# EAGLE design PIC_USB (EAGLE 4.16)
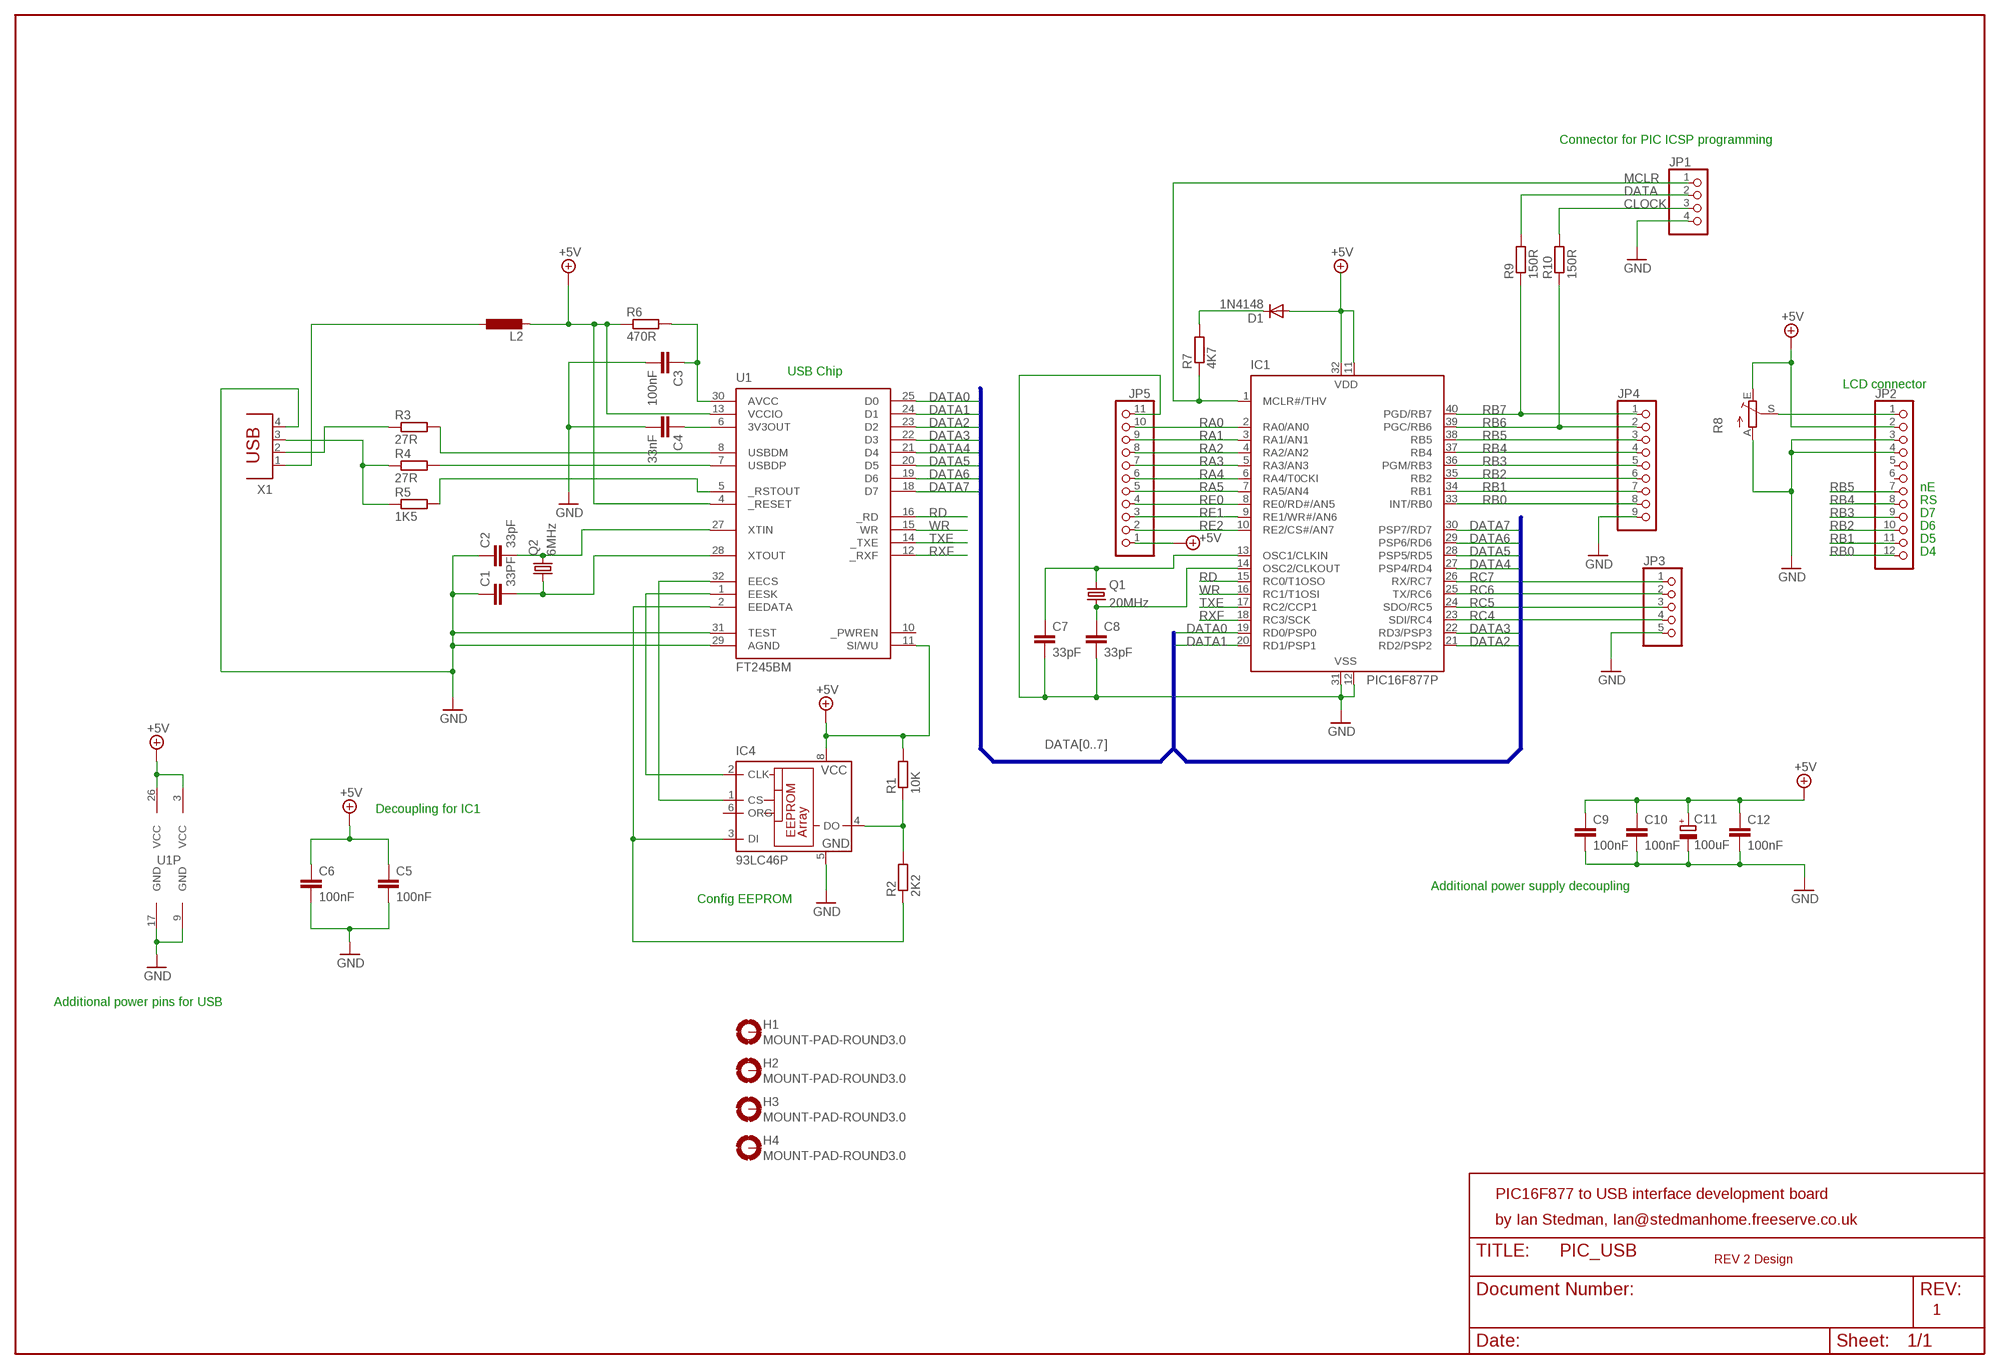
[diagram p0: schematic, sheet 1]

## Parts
C1  33PF  C-EU025-025X050  [C025-025X050]
C2  33pF  C-EU025-025X050  [C025-025X050]
C3  100nF  C-EU050-025X075  [C050-025X075]
C4  33nF  C-EU050-025X075  [C050-025X075]
C5  100nF  C-EU050-025X075  [C050-025X075]
C6  100nF  C-EU050-025X075  [C050-025X075]
C7  33pF  C-EU025-025X050  [C025-025X050]
C8  33pF  C-EU025-025X050  [C025-025X050]
C9  100nF  C-EU050-025X075  [C050-025X075]
C10  100nF  C-EU050-025X075  [C050-025X075]
C11  100uF  CPOL-EUE5-10.5  [E5-10,5]
C12  100nF  C-EU050-025X075  [C050-025X075]
D1  1N4148  [DO35-10]
H1  MOUNT-PAD-ROUND3.0  [3,0-PAD]
H2  MOUNT-PAD-ROUND3.0  [3,0-PAD]
H3  MOUNT-PAD-ROUND3.0  [3,0-PAD]
H4  MOUNT-PAD-ROUND3.0  [3,0-PAD]
IC1  PIC16F877P  [DIL40]
IC4  93LC46P  [DIL8]
JP1  PINHD-1X4  [1X04]
JP2  PINHD-1X12  [1X12]
JP3  PINHD-1X5  [1X05]
JP4  PINHD-1X9  [1X09]
JP5  PINHD-1X11  [1X11]
L2  L-EU0207/10  [0207/10]
Q1  20MHz  CRYTALHC49U-V  [HC49U-V]
Q2  6MHz  CRYTALHC49U-V  [HC49U-V]
R1  10K  R-EU_0207/7  [0207/7]
R2  2K2  R-EU_0207/7  [0207/7]
R3  27R  R-EU_0207/7  [0207/7]
R4  27R  R-EU_0207/7  [0207/7]
R5  1K5  R-EU_0207/7  [0207/7]
R6  470R  R-EU_0207/7  [0207/7]
R7  4K7  R-EU_0207/7  [0207/7]
R8  TRIM_EU-CA6V  [CA6V]
R9  150R  R-EU_0207/2V  [0207/2V]
R10  150R  R-EU_0207/5V  [0207/5V]
U1  FT245BM  [LQFP32]
X1  PN61729  [PN61729]

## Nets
3V3OUT: C4.1 U1.6(3V3OUT)
+5V: C5.1 C6.1 C9.1 C10.1 C11.+ C12.1 D1.A IC1.11(VDD) IC1.32(VDD) IC4.8(VCC) JP2.2 JP5.1 L2.2 R1.2 R6.1 R8.E U1.3(VCC) U1.4(_RESET) U1.11(SI/WU) U1.13(VCCIO) U1.26(VCC)
AVCC: C3.1 R6.2 U1.30(AVCC)
CLOCK: JP1.3 R10.2
DATA: JP1.2 R9.2
DATA0: IC1.19(RD0/PSP0) U1.25(D0)
DATA1: IC1.20(RD1/PSP1) U1.24(D1)
DATA2: IC1.21(RD2/PSP2) U1.23(D2)
DATA3: IC1.22(RD3/PSP3) U1.22(D3)
DATA4: IC1.27(PSP4/RD4) U1.21(D4)
DATA5: IC1.28(PSP5/RD5) U1.20(D5)
DATA6: IC1.29(PSP6/RD6) U1.19(D6)
DATA7: IC1.30(PSP7/RD7) U1.18(D7)
GND: C1.1 C2.1 C3.2 C4.2 C5.2 C6.2 C7.2 C8.2 C9.2 C10.2 C11.- C12.2 IC1.12(VSS) IC1.31(VSS) IC4.5(GND) JP1.4 JP2.3 JP2.4 JP3.5 JP4.9 JP5.11 R8.A U1.9(GND) U1.17(GND) U1.29(AGND) U1.31(TEST) X1.4
MCLR: IC1.1(MCLR#/THV) JP1.1 R7.1
N$1: D1.C R7.2
N$2: C1.2 Q2.1 U1.28(XTOUT)
N$3: C7.1 IC1.13(OSC1/CLKIN) Q1.2
N$5: JP2.1 R8.S
N$8: C2.2 Q2.2 U1.27(XTIN)
N$9: C8.1 IC1.14(OSC2/CLKOUT) Q1.1
N$10: IC4.1(CS) U1.32(EECS)
N$11: IC4.2(CLK) U1.1(EESK)
N$12: IC4.3(DI) R2.1 U1.2(EEDATA)
N$15: IC4.4(DO) R1.1 R2.2
N$19: R3.2 U1.8(USBDM)
N$20: R4.2 U1.7(USBDP)
N$22: R5.2 U1.5(_RSTOUT)
PWRIN: L2.1 X1.1
RA0: IC1.2(RA0/AN0) JP5.10
RA1: IC1.3(RA1/AN1) JP5.9
RA2: IC1.4(RA2/AN2) JP5.8
RA3: IC1.5(RA3/AN3) JP5.7
RA4: IC1.6(RA4/T0CKI) JP5.6
RA5: IC1.7(RA5/AN4) JP5.5
RB0: IC1.33(INT/RB0) JP2.12 JP4.8
RB1: IC1.34(RB1) JP2.11 JP4.7
RB2: IC1.35(RB2) JP2.10 JP4.6
RB3: IC1.36(PGM/RB3) JP2.9 JP4.5
RB4: IC1.37(RB4) JP2.8 JP4.4
RB5: IC1.38(RB5) JP2.7 JP4.3
RB6: IC1.39(PGC/RB6) JP4.2 R10.1
RB7: IC1.40(PGD/RB7) JP4.1 R9.1
RC4: IC1.23(SDI/RC4) JP3.4
RC5: IC1.24(SDO/RC5) JP3.3
RC6: IC1.25(TX/RC6) JP3.2
RC7: IC1.26(RX/RC7) JP3.1
RD: IC1.15(RC0/T1OSO) U1.16(_RD)
RE0: IC1.8(RE0/RD#/AN5) JP5.4
RE1: IC1.9(RE1/WR#/AN6) JP5.3
RE2: IC1.10(RE2/CS#/AN7) JP5.2
RXF: IC1.18(RC3/SCK) U1.12(_RXF)
TXE: IC1.17(RC2/CCP1) U1.14(_TXE)
USBM: R3.1 X1.2
USBP: R4.1 R5.1 X1.3
WR: IC1.16(RC1/T1OSI) U1.15(WR)
Unconnected: H1.B3,0(MOUNT) H2.B3,0(MOUNT) H3.B3,0(MOUNT) H4.B3,0(MOUNT) IC4.6(ORG) IC4.7(NU) JP2.5 JP2.6 U1.10(_PWREN)

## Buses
DATA[0..7]

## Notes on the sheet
- Connector for PIC ICSP programming
- USB Chip
- LCD connector
- nE
- RS
- D7
- D6
- D5
- D4
- Decoupling for IC1
- Additional power supply decoupling
- Config EEPROM
- Additional power pins for USB
- PIC16F877 to USB interface development board
- by Ian Stedman, Ian@stedmanhome.freeserve.co.uk
- REV 2 Design
- 1

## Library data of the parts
C1-C10 C12 = rcl:C-EU: CAPACITOR, European symbol
C11 = rcl:CPOL-EU: POLARIZED CAPACITOR, European symbol
D1 = diode:1N4148: DIODE
H1-H4 = holes:MOUNT-PAD-ROUND: MOUNTING PAD, round
IC1 = microchip:PIC16F87*: MICROCONTROLLER
IC4 = microchip:93*: Serial EPROM 1 K/2 K/4 K, low voltage, Microwire
JP1 = pinhead:PINHD-1X4: PIN HEADER
JP2 = pinhead:PINHD-1X12: PIN HEADER
JP3 = pinhead:PINHD-1X5: PIN HEADER
JP4 = pinhead:PINHD-1X9: PIN HEADER
JP5 = pinhead:PINHD-1X11: PIN HEADER
L2 = rcl:L-EU: INDUCTOR, European symbol
Q1 Q2 = crystal:CRYTAL: CRYSTAL
R1-R7 R9 R10 = rcl:R-EU_: RESISTOR, European symbol
R8 = pot:TRIM_EU-: POTENTIOMETER
U1 = ftdi3:FT245BM: USB FIFO 2nd Generation USB FIFO (USB <-> Parallel)
X1 = con-berg:PN61729: BERG

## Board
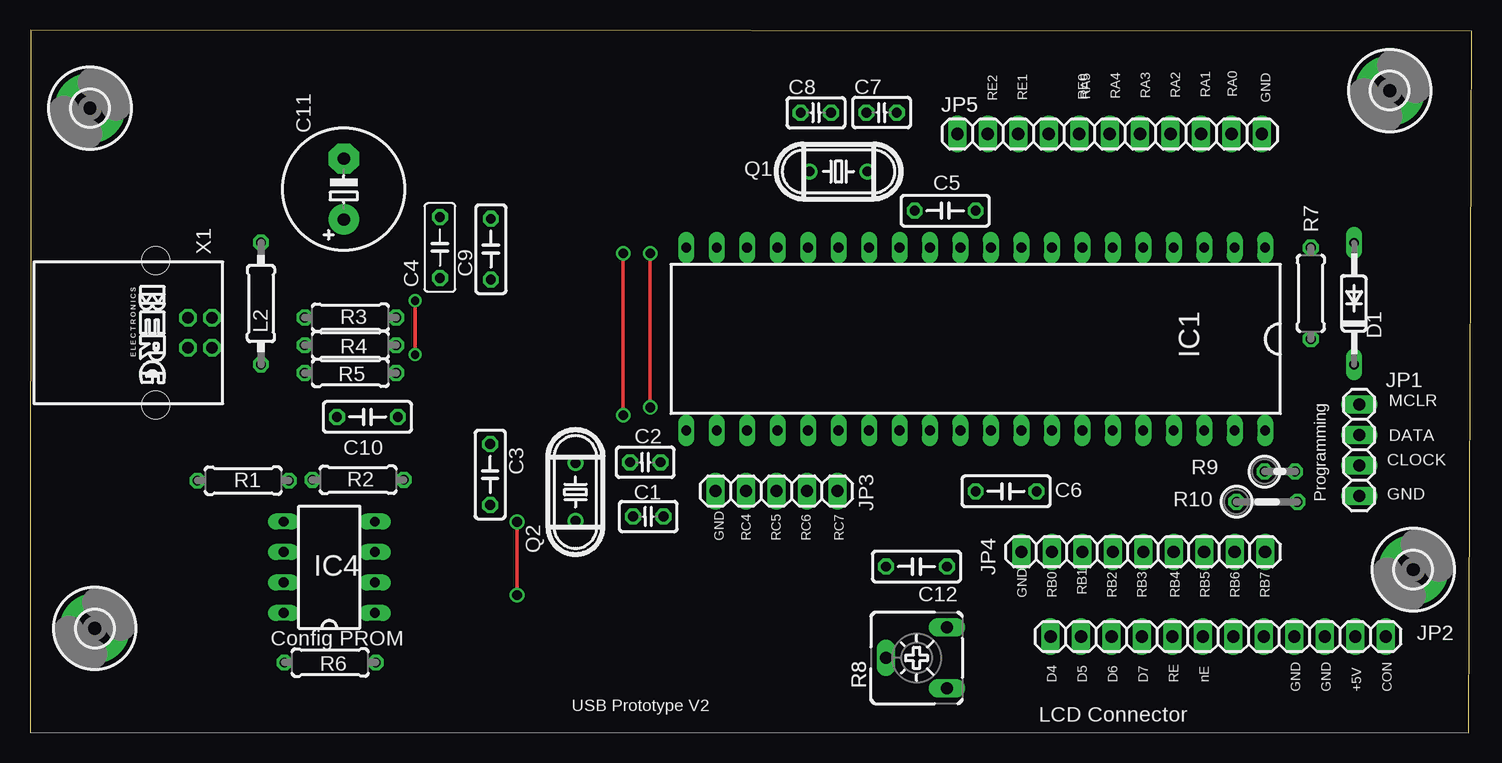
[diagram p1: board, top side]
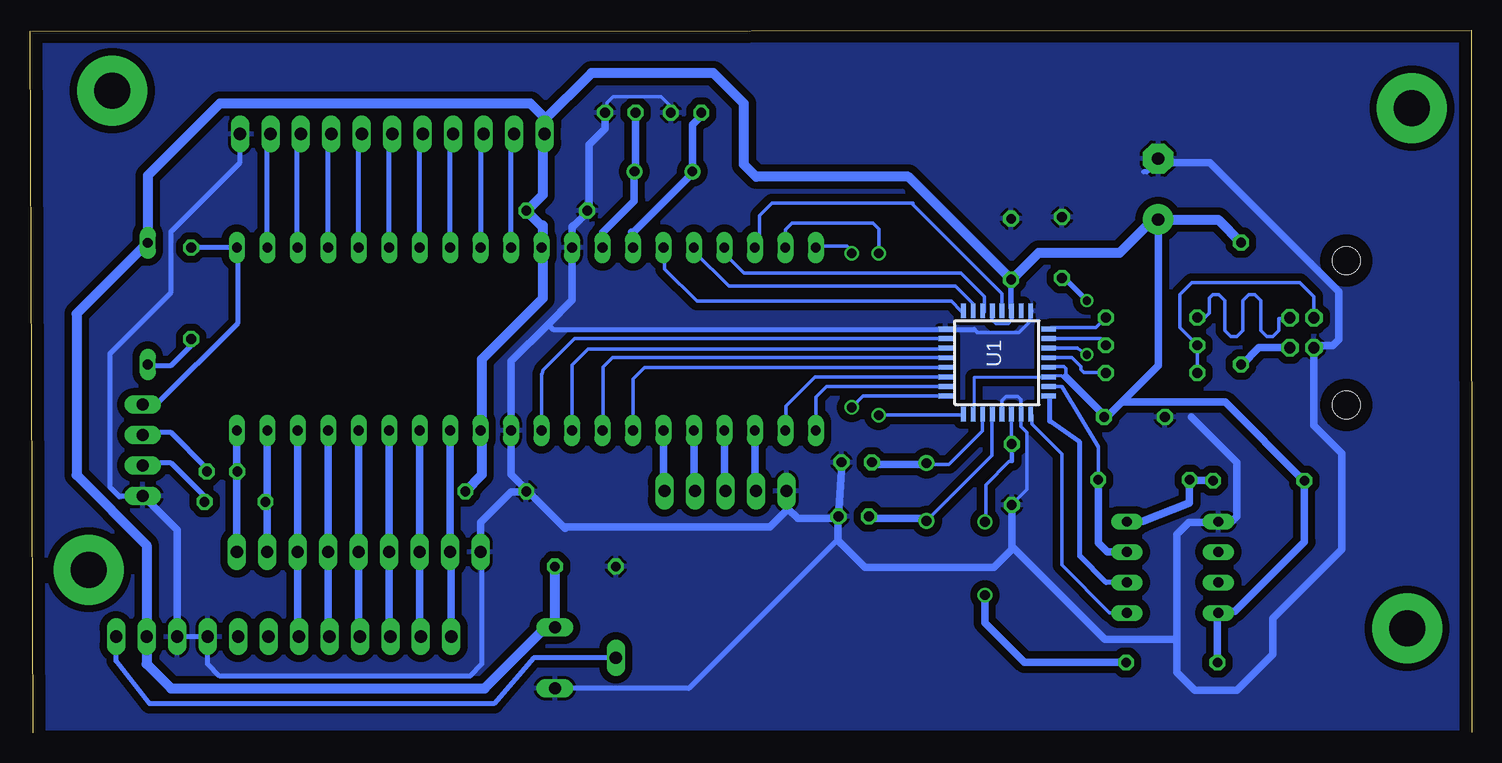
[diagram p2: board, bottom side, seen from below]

Size 120.2 x 58.59 mm. Coordinates in mm from the lower left corner, seen from the top.
Outline: 119.94,0 120.2,58.5 0.05,58.59 0,0.04
Copper layers (1*16): Top 0.035mm / dielectric 1.5mm / Bottom 0.035mm
Design rules "10mils": minimum track width 10mil, minimum drill 24mil, track to track 10mil, track to pad 10mil, pad to pad 10mil, via to via 10mil, smd to smd 10mil, copper to edge 40mil, drill to drill 10mil, minimum pad ring 10mil, minimum via ring 8mil, stop-mask expansion 0mil, vias tented up to drill 0mil, thermal gap 10mil

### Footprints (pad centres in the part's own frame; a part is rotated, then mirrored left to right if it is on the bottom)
C025-025X050 = drill 0.813 octagon: 1 -1.27,0; 2 1.27,0
C050-025X075 = drill 0.813 octagon: 1 -2.54,0; 2 2.54,0
E5-10,5 = drill 1.016 pad 2.54 round: + -2.54,0 | drill 1.016 pad 2.54 octagon: - 2.54,0
DO35-10 = drill 0.813 long: A 5.08,0; C -5.08,0
3,0-PAD = drill 3 pad 5.842 round: B3,0 0,0
DIL40 = drill 0.813 long: 1 -24.13,-7.62; 2 -21.59,-7.62; 3 -19.05,-7.62; 4 -16.51,-7.62; 5 -13.97,-7.62; 6 -11.43,-7.62; 7 -8.89,-7.62; 8 -6.35,-7.62; 9 -3.81,-7.62; 10 -1.27,-7.62; 11 1.27,-7.62; 12 3.81,-7.62; 13 6.35,-7.62; 14 8.89,-7.62; 15 11.43,-7.62; 16 13.97,-7.62; 17 16.51,-7.62; 18 19.05,-7.62; 19 21.59,-7.62; 20 24.13,-7.62; 21 24.13,7.62; 22 21.59,7.62; 23 19.05,7.62; 24 16.51,7.62; 25 13.97,7.62; 26 11.43,7.62; 27 8.89,7.62; 28 6.35,7.62; 29 3.81,7.62; 30 1.27,7.62; 31 -1.27,7.62; 32 -3.81,7.62; 33 -6.35,7.62; 34 -8.89,7.62; 35 -11.43,7.62; 36 -13.97,7.62; 37 -16.51,7.62; 38 -19.05,7.62; 39 -21.59,7.62; 40 -24.13,7.62
DIL8 = drill 0.813 long: 1 -3.81,-3.81; 2 -1.27,-3.81; 3 1.27,-3.81; 4 3.81,-3.81; 5 3.81,3.81; 6 1.27,3.81; 7 -1.27,3.81; 8 -3.81,3.81
1X04 = drill 1.016 long: 1 -3.81,0; 2 -1.27,0; 3 1.27,0; 4 3.81,0
1X12 = drill 1.016 long: 1 -13.97,0; 2 -11.43,0; 3 -8.89,0; 4 -6.35,0; 5 -3.81,0; 6 -1.27,0; 7 1.27,0; 8 3.81,0; 9 6.35,0; 10 8.89,0; 11 11.43,0; 12 13.97,0
1X05 = drill 1.016 long: 1 -5.08,0; 2 -2.54,0; 3 0,0; 4 2.54,0; 5 5.08,0
1X09 = drill 1.016 long: 1 -10.16,0; 2 -7.62,0; 3 -5.08,0; 4 -2.54,0; 5 0,0; 6 2.54,0; 7 5.08,0; 8 7.62,0; 9 10.16,0
1X11 = drill 1.016 long: 1 -12.7,0; 2 -10.16,0; 3 -7.62,0; 4 -5.08,0; 5 -2.54,0; 6 0,0; 7 2.54,0; 8 5.08,0; 9 7.62,0; 10 10.16,0; 11 12.7,0
0207/10 = drill 0.813 octagon: 1 -5.08,0; 2 5.08,0
HC49U-V = drill 0.813 round: 1 -2.413,0; 2 2.413,0
0207/7 = drill 0.813 octagon: 1 -3.81,0; 2 3.81,0
CA6V = drill 1.016 long: A -2.54,-2.54; E 2.54,-2.54; S 0,2.54
0207/2V = drill 0.813 octagon: 1 -1.27,0; 2 1.27,0
0207/5V = drill 0.813 octagon: 1 -2.54,0; 2 2.54,0
LQFP32 = smd 0.4 x 1.2: 1 -2.8,-4.3; 2 -2,-4.3; 3 -1.2,-4.3; 4 -0.4,-4.3; 5 0.4,-4.3; 6 1.2,-4.3; 7 2,-4.3; 8 2.8,-4.3; 17 2.8,4.3; 18 2,4.3; 19 1.2,4.3; 20 0.4,4.3; 21 -0.4,4.3; 22 -1.2,4.3; 23 -2,4.3; 24 -2.8,4.3 | smd 1.2 x 0.4: 9 4.3,-2.8; 10 4.3,-2; 11 4.3,-1.2; 12 4.3,-0.4; 13 4.3,0.4; 14 4.3,1.2; 15 4.3,2; 16 4.3,2.8; 25 -4.3,2.8; 26 -4.3,2; 27 -4.3,1.2; 28 -4.3,0.4; 29 -4.3,-0.4; 30 -4.3,-1.2; 31 -4.3,-2; 32 -4.3,-2.8
PN61729 = drill 0.95 octagon: 1 1.25,4.71; 2 -1.25,4.71; 3 -1.25,2.71; 4 1.25,2.71 | hole 2.3: -6.02,0; 6.02,0

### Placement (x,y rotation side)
C1  51.54,18.02 180 top
C2  51.29,22.54 180 top
C3  38.36,21.52 270 top
C4  34.17,40.45 90 top
C5  76.29,43.52 180 top
C6  81.37,20.12 180 top
C7  70.99,51.7 0 top
C8  65.51,51.69 0 top
C9  38.42,40.31 90 top
C10  28.13,26.32 180 top
C11  26.16,45.32 90 top
C12  73.9,13.85 180 top
D1  110.38,35.77 90 top
H1  5,52.07 0 top
H2  5.4,8.69 0 top
H3  115.31,13.58 0 top
H4  113.35,53.53 0 top
IC1  78.83,32.82 180 top
IC4  24.95,13.79 90 top
JP1  110.81,23.55 270 top
JP2  99.05,8.01 180 top
JP3  62.23,20.14 180 top
JP4  92.8,15.07 180 top
JP5  90,49.92 0 top
L2  19.25,35.78 90 top
Q1  67.4,46.79 0 top
Q2  45.47,20.06 90 top
R1  17.77,21.01 180 top
R2  27.35,21.08 180 top
R3  26.71,34.61 0 top
R4  26.71,32.3 0 top
R5  26.71,29.99 0 top
R6  25.02,5.84 0 top
R7  106.77,36.63 270 top
R8  73.9,6.23 90 top
R9  104.19,21.77 0 top
R10  103.11,19.24 0 top
U1  39.58,30.86 90 bottom
X1  10.47,33.34 270 top

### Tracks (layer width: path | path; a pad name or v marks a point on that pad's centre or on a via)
3V3OUT  (via drill 0.7)
  Top 0.305: v32.1,31.52 v32.1,36.02
  Bottom 0.305: U1.6 32.89,32.06 32.85,32.02 v32.1,31.52
  Bottom 0.406: 34.28,37.98 34.24,37.98 | 34.24,37.98 C4.1 | v32.1,36.02 34.06,37.98 34.24,37.98
+5V
  Bottom 0.254: 39.7,34.12 38.9,34.12 38.85,34.17 38.6,34.17 38.34,34.42 38.34,37.22 38.6,37.47 36.06,40.01 29.45,40.01 26.91,42.55 26.41,42.55 26.15,42.8 | U1.26 41.5,27.12 41.5,29.62 35.8,29.62 U1.3 34.7,29.72 34.2,29.72 34.11,29.66
  Bottom 0.305: 38.42,35.09 38.4,35.07 38.38,35.09 U1.11 38.38,34.39 38.65,34.12 39.7,34.12 40,34.42 40,35.02 39.98,35.04 U1.13 | U1.4 35.26,30.46 35.2,30.52 34,30.52 33.85,30.37 33.85,29.92 34.11,29.66 33.84,29.66 | 13.9,21.02 13.91,21.01 R1.2 | 30.67,26.49 C10.1 30.44,26.32 30.22,26.55 29.2,27.56 | 77.46,42.3 77.97,42.3 78.98,43.31
  Bottom 0.406: U1.11 38.38,35.24 38.35,35.27 38.42,35.34 C9.1 | D1.A 110.4,40.85 | JP2.2 110.73,8.26
  Bottom 0.61: 21.01,9.98 21,9.97 21.21,9.76 R6.1 | 21.01,9.98 IC4.8 | 13.61,21.01 R1.2 13.96,20.96 | 13.96,20.96 13.96,15.91 19.75,10.12 21.25,10.12 21.11,9.98 21.01,9.98 | 38.6,38.02 38.42,37.84 C9.1 38.39,37.77 38.34,37.72 | 26.35,42.77 C11.+ | 77.46,49.92 77.46,51.44 | 78.83,43.47 78.98,43.31 | 78.83,43.47 C5.1 | 77.46,44.84 78.83,43.47 | 77.46,42.15 77.46,40.34 | 82.54,25.1 IC1.32 82.54,25.3 | 77.46,40.34 IC1.11 | 77.46,36.2 77.46,40.34 | 30.67,26.49 33.84,29.66 | 29.2,27.56 20.56,27.56 13.96,20.96 | 26.15,42.8 26.15,30.61 30.22,26.55
  Bottom 0.813: L2.2 21.16,42.77 C11.+ | 26.35,42.77 26.6,42.77 29.35,40.02 36.1,40.02 38.35,37.77 C9.1 | D1.A 110.38,46.46 104.38,52.46 78.48,52.46 77.46,51.44 | 77.46,49.92 JP5.1 | 77.46,49.92 77.46,44.84 78.98,43.31 | C5.1 77.46,42.15 | C6.1 82.54,21.49 82.54,25.1 | 82.54,25.3 82.54,31.12 77.46,36.2 77.46,42.3 | 77.46,49.92 77.46,50.93 73.4,55 63.24,55 60.7,52.46 60.7,47.38 59.68,46.36 46.98,46.36 38.39,37.77 | 110.4,40.85 116.32,34.93 116.32,21.47 110.48,15.63 JP2.2 110.48,5.72 108.45,3.69 82.29,3.69 77.21,8.77 R8.E C12.1
AVCC  (via drill 0.81)
  Top 0.305: v40.6,11.47 v40.6,17.57
  Bottom 0.305: 38.32,22.59 C3.1 | U1.30 38.38,22.65 38.32,22.59 | 38.32,22.59 38.58,22.59 40.5,20.67 40.5,17.67 v40.6,17.57
  Bottom 0.61: v40.6,11.47 40.6,9.17 37.3,5.87 29,5.87 28.9,5.77 R6.2
CLOCK
  Bottom 0.406: R10.2 105.65,19.69 108.45,22.48 110.99,22.48 110.81,22.31 JP1.3
DATA
  Bottom 0.406: R9.2 105.46,22.04 108.45,25.02 110.99,25.02 110.81,24.85 JP1.2
DATA0  (via drill 0.81)
  Top 0.305: v49.45,26.47 v49.45,39.97
  Bottom 0.305: IC1.19 57.24,41.93 56.7,42.47 49.95,42.47 49.45,41.97 v49.45,39.97 | U1.25 42.38,26.54 42.45,26.47 v49.45,26.47
DATA1  (via drill 0.81, 0.81 pad 0.61)
  Top 0.305: v51.7,27.12 v51.7,39.97
  Bottom 0.305: IC1.20 54.57,40.57 52.1,40.57 51.7,40.17 v51.7,39.97 | U1.24 50.75,28.07 v51.7,27.12
DATA2
  Bottom 0.305: U1.23 53.81,28.86 54.7,27.97 IC1.21 54.7,24.97
DATA3
  Bottom 0.305: U1.22 54.76,29.66 57.2,27.22 57.2,24.97 57.24,25.01 IC1.22
DATA4
  Bottom 0.305: U1.21 68.96,30.46 69.95,29.47 69.95,25.22 IC1.27
DATA5
  Bottom 0.305: U1.20 71.66,31.26 72.45,30.47 72.45,24.97 72.48,25 IC1.28
DATA6
  Bottom 0.305: IC1.29 75.02,30.65 73.7,31.97 44.2,31.97 44.11,32.06 U1.19
DATA7
  Bottom 0.305: IC1.30 77.56,29.91 77.51,29.91 77.45,30.22 74.81,32.86 U1.18
GND
  Bottom 0.254: 21.1,17.52 21.15,17.57 | 21.1,17.52 IC4.5 | 21.1,17.52 | 37.6,25.52 37.6,27.77 | 80.1,25.07 80.1,25.22 | U1.17 43.9,33.72 43.9,33.62 | U1.9 36.8,35.22 36.73,35.14
  Bottom 0.305: 41.49,33.66 41.2,33.37 37.75,33.37 | 37.75,33.37 36.85,34.27 36.85,35.02 36.73,35.14 36.7,35.17 | 72.6,50.02 72.26,50.36 | 37.75,33.37 41.25,33.37 41.5,33.62 | C3.2 38.36,19.01 38.35,19.02 37.1,20.27 37.1,25.02 37.6,25.52 37.6,26.52 | U1.29 39.18,27.69 38.85,28.02 37.85,28.02 37.6,27.77 37.6,26.52 | 37.6,26.52 37.58,26.54 U1.31 | C8.2 66.78,52.2 67.6,53.02 71.6,53.02 72.1,52.52 72.1,51.52 72.26,51.68 C7.2
  Bottom 0.406: 41.5,33.62 43.9,33.62 76.6,33.62 77.02,34.05 | 38.35,15.52 38.35,19.02 | 27.35,46.77 27.1,46.77 26.35,47.52 | JP2.4 JP2.3 | JP2.4 104.89,8.01 104.89,7.75 105.4,8.26 JP2.4 | JP2.4 105.4,5.72 104.38,4.7 83.56,4.7 82.54,5.72 82.54,15.37 82.64,15.27 JP4.9 | JP5.11 102.7,47.54 108.45,41.79 108.45,36.71 113.53,31.63 113.53,20.45 112.77,19.69 110.73,19.69 110.78,19.74 JP1.4 | 52.85,16.02 52.94,16.02 65.27,3.69 R8.A
  Bottom 0.61: JP4.9 82.64,17.53 80.1,20.07 79.15,20.07 79.1,20.02 79,20.12 C6.2 78.7,20.12 | 57,18.67 58.5,17.17 75.6,17.17 75.6,17.02 78.7,20.12 | JP3.5 57.07,20.14 57,20.07 57,18.67 | 80.03,25.2 80,25.17 80.1,25.07 | 80.1,25.07 IC1.31 80.1,25.22 80.1,30.97 77.02,34.05 75.02,36.05 IC1.12 | 57,18.67 56.2,17.87 52.7,17.87 52.55,18.02 C1.1 | 52.51,22.46 52.56,22.41 C2.1 | C1.1 52.51,22.46 | 52.51,22.46 52.5,22.47 | 21.25,17.47 21.15,17.57 21.1,17.62 20.2,17.62 20.1,17.52 19.6,18.02 19.6,22.52 23.4,26.32 | 72.37,50.25 72.6,50.02 73.6,49.02 73.6,43.52 | 73.6,43.52 C5.2 | 74.87,42.25 73.6,43.52 | 74.87,42.25 75.02,42.1 | 78.7,20.12 78.6,20.02 | 80.1,25.07 80.1,21.52 78.7,20.12 | C9.2 38.57,42.99 38.6,43.02 | 24.6,7.77 24.6,5.02 23.1,3.52 19.6,3.52 16.6,6.52 16.6,9.52 10.85,15.27 10.85,23.27 13.18,25.6 X1.4 13.18,32.19 13.1,32.27 11.6,32.27 11.1,32.77 11.1,36.77 21.85,47.52 26.35,47.52 | 24.6,7.77 24.6,16.52 23.6,17.52 21.1,17.52 21.14,17.56 IC4.5 | 38.35,15.52 30.6,7.77 24.6,7.77 | 38.35,19.02 38.35,15.27 39.85,13.77 50.6,13.77 52.85,16.02 52.85,18.02 C1.1 | 72.26,51.83 C7.2 | 72.26,50.36 72.26,51.83 | 72.26,51.83 72.38,51.95 | IC1.12 75.02,40.67 74.92,40.77 | 74.87,42.25 74.92,42.3 75.02,42.2 IC1.12 | 110.81,19.77 110.99,19.94 | 110.81,19.77 JP1.4 | JP2.3 107.94,16.9 110.73,19.69 110.81,19.77
  pour Bottom (isolate 0.61): 0.24,58.3 119.88,58.3 119.88,0.39 0.24,0.39
MCLR
  Bottom 0.406: 106.77,40.42 106.92,40.26 | 106.77,40.42 R7.1 | 106.77,40.42 106.75,40.44 IC1.1 102.96,40.67 102.86,40.77 102.86,34.17 109.67,27.36 JP1.1
N$1
  Bottom 0.406: R7.2 106.77,32.29 108.45,30.61 110.48,30.61 110.4,30.69 D1.C
N$2
  Bottom 0.305: U1.28 40,26.54 40,23.12 Q2.1
  Bottom 0.61: C1.2 50,17.99 50,17.87 45.69,17.87 Q2.1
N$3
  Bottom 0.61: IC1.13 72.48,41.69 69.84,44.33 69.84,46.87 | 69.84,46.87 69.81,46.84 Q1.2 | C7.1 69.72,46.99 69.84,46.87
N$5
  Bottom 0.406: R8.S 78.22,6.23 81.52,2.42 110.23,2.42 113.02,5.97 JP2.1
N$8
  Bottom 0.305: U1.27 40.78,26.49 40.8,26.47 40.8,25.17 43.6,22.37 45.37,22.37 Q2.2
  Bottom 0.61: C2.2 50,22.37 45.57,22.37 Q2.2
N$9
  Bottom 0.61: IC1.14 70.01,40.37 70.05,40.37 70.05,41.73 69.9,41.73 64.84,46.79 | 64.84,46.79 64.76,46.87 | 64.84,46.79 Q1.1 64.99,50.7 64.24,51.45 C8.1
N$10
  Bottom 0.305: IC4.1 30.21,9.98 34.2,13.97 34.2,23.22 36.7,25.72 36.7,26.47 U1.32
N$11
  Bottom 0.305: 35.2,27.97 U1.1
  Bottom 0.406: IC4.2 30.5,12.52 32.7,14.72 32.7,24.22 35.2,25.97 35.2,27.97
N$12
  Bottom 0.305: U1.2 35.21,28.86 35.2,28.87 34.2,28.87 31.16,23.83 31.16,23.73 31.15,23.72 31.16,23.71 R2.1
  Bottom 0.61: IC4.3 30.39,15.06 31.15,15.82 31.15,21.02 31.16,21.03 R2.1
N$15
  Bottom 0.61: IC4.4 27.47,17.6 23.55,19.17 23.55,20.47 R2.2 23.59,21.08 23.65,21.02 23.64,21.01 R1.1
N$19
  Bottom 0.305: R3.2 31.35,33.77 35.1,33.77 35.21,33.66 U1.8
N$20
  Bottom 0.305: 30.38,32.3 30.35,32.27 | R4.2 30.38,32.3 | U1.7 30.94,32.86 30.38,32.3
N$22
  Bottom 0.305: 30.57,29.99 R5.2 30.55,30.02 32.35,30.02 32.6,30.27 32.6,30.52 33.35,31.27 33.83,31.27 33.84,31.26 U1.5
PWRIN
  Bottom 0.61: L2.1 19.23,30.7 19.2,30.67 17.78,32.09 X1.1
RA0
  Bottom 0.406: JP5.10 100.16,50.01 100.32,50.17 100.42,50.07 IC1.2
RA1
  Bottom 0.254: 97.88,40.54 97.9,40.62 IC1.3
  Bottom 0.406: 97.88,40.54 97.85,40.54 | JP5.9 97.62,50.01 97.78,50.17 97.95,50 97.95,40.47
  Bottom 0.61: 97.95,40.47 97.92,40.44 IC1.3
RA2
  Bottom 0.406: JP5.8 95.08,50.01 95.24,50.17 95.34,50.07 IC1.4
RA3
  Bottom 0.254: 92.7,40.47 92.7,40.52 IC1.5
  Bottom 0.406: JP5.7 92.54,50.01 92.7,50.17 92.8,50.07 IC1.5
  Bottom 0.61: 92.7,40.47 92.73,40.44
RA4
  Bottom 0.406: JP5.6 90,50.01 90.16,50.17 90.26,50.07 IC1.6
RA5
  Bottom 0.406: JP5.5 87.46,50.01 87.62,50.17 87.72,50.07 IC1.7
RB0
  Bottom 0.61: IC1.33 JP4.8 85.18,14.96 85.08,14.86 JP2.12
RB1
  Bottom 0.61: JP4.7 87.72,14.96 87.62,14.86 | JP4.7 IC1.34 | JP2.11 87.62,7.75 87.72,7.85 JP4.7
RB2
  Bottom 0.61: JP4.6 90.26,14.96 90.16,14.86 | JP4.6 IC1.35 | JP2.10 90.16,7.75 90.26,7.85 JP4.6
RB3
  Bottom 0.61: JP4.5 92.8,14.96 92.7,14.86 | JP4.5 IC1.36 | JP2.9 92.7,7.75 92.8,7.85 JP4.5
RB4
  Bottom 0.61: JP4.4 95.34,14.96 95.24,14.86 | JP4.4 IC1.37 | JP2.8 95.24,7.75 95.34,7.85 JP4.4
RB5
  Bottom 0.61: JP4.3 97.88,14.96 97.78,14.86 | JP4.3 IC1.38 | JP2.7 97.78,7.75 97.88,7.85 JP4.3
RB6
  Bottom 0.61: JP4.2 IC1.39 | JP4.2 100.42,14.99 100.35,14.92 | 100.63,19.24 100.83,19.44 | 100.63,19.24 R10.1 | JP4.2 100.42,19.03 100.63,19.24
RB7
  Bottom 0.254: R9.1 102.9,21.82 102.96,21.82
  Bottom 0.61: 102.92,14.89 102.96,14.93 JP4.1 102.96,21.82 102.96,25.31 | 102.96,25.31 IC1.40 | 102.96,25.31 102.95,25.32
RC4
  Bottom 0.61: JP3.4 59.69,19.98 59.7,19.97 59.78,20.05 IC1.23
RC5
  Bottom 0.61: 62.12,20.14 61.95,19.97 | 62.12,20.14 JP3.3 | IC1.24 62.32,20.34 62.12,20.14
RC6
  Bottom 0.61: 64.7,19.97 64.77,20.04 | 64.77,20.04 JP3.2 | IC1.25 64.86,20.13 64.77,20.04
RC7
  Bottom 0.61: IC1.26 67.4,20.17 66.95,19.72 67.2,19.72 67.31,19.83 JP3.1
RD
  Bottom 0.305: U1.16 42.59,35.16 43.4,35.97 64.6,35.97 67.3,38.67 67.3,40.67 67.4,40.77 IC1.15
RE0
  Bottom 0.406: JP5.4 84.92,50.01 85.08,50.17 85.18,50.07 IC1.8
RE1
  Bottom 0.406: 82.6,40.44 82.6,40.27 | IC1.9 82.6,40.44 | JP5.3 82.38,50.01 82.54,50.17 82.6,50.11 82.6,40.44
  Bottom 0.61: IC1.9 82.64,40.41
RE2
  Bottom 0.406: 80.1,40.27 IC1.10 80.1,50.07 80,50.17 79.84,50.01 JP5.2
  Bottom 0.61: IC1.10 80.1,40.32
RXF
  Bottom 0.305: IC1.18 59.57,40.44 59.4,40.27 59.4,43.12 58.35,44.17 46.6,44.17 46.6,44.02 39.18,36.6 U1.12
TXE
  Bottom 0.305: IC1.17 62.32,39.94 60.7,38.32 42.6,38.32 40.65,36.37 40.65,35.07 40.74,35.16 U1.14
USBM
  Bottom 0.305: X1.2 15.1,34.52 16.1,34.52 16.1,33.52 16.6,33.02 17.1,33.02 17.6,33.52 17.6,36.02 18.1,36.52 18.6,36.52 19.1,36.02 19.1,33.52 19.6,33.02 20.1,33.02 20.6,33.52 20.6,36.02 21.1,36.52 21.6,36.52 21.9,36.22 21.9,34.97 22.35,34.52 22.85,34.52 22.9,34.57 R3.1
USBP
  Bottom 0.305: X1.3 13.18,36.35 14.35,37.52 23.35,37.52 24.35,36.52 24.35,33.77 22.88,32.3 | 22.88,32.3 22.85,32.27 | 22.88,32.3 R4.1 22.9,29.82 | 22.9,29.82 R5.1 | 22.9,29.82 22.85,29.77
WR
  Bottom 0.305: IC1.16 64.86,40.13 61.95,37.22 43.05,37.22 41.6,35.77 41.6,35.17 U1.15

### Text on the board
tPlace: E L E C T R O N I C S
tNames: GND | RE2 | RE1 | RE0 | RA5 | RA4 | RA3 | RA2 | RA1 | RA0 | JP5 | MCLR | DATA | CLOCK | Programming | GND | GND | RC4 | RC5 | RC6 | RC7 | GND | RB0 | RB1 | RB2 | RB3 | RB4 | RB5 | RB6 | RB7 | Config PROM | R8 | D4 | D5 | D6 | D7 | RE | nE | GND | GND | +5V | CON | USB Prototype V2 | LCD Connector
